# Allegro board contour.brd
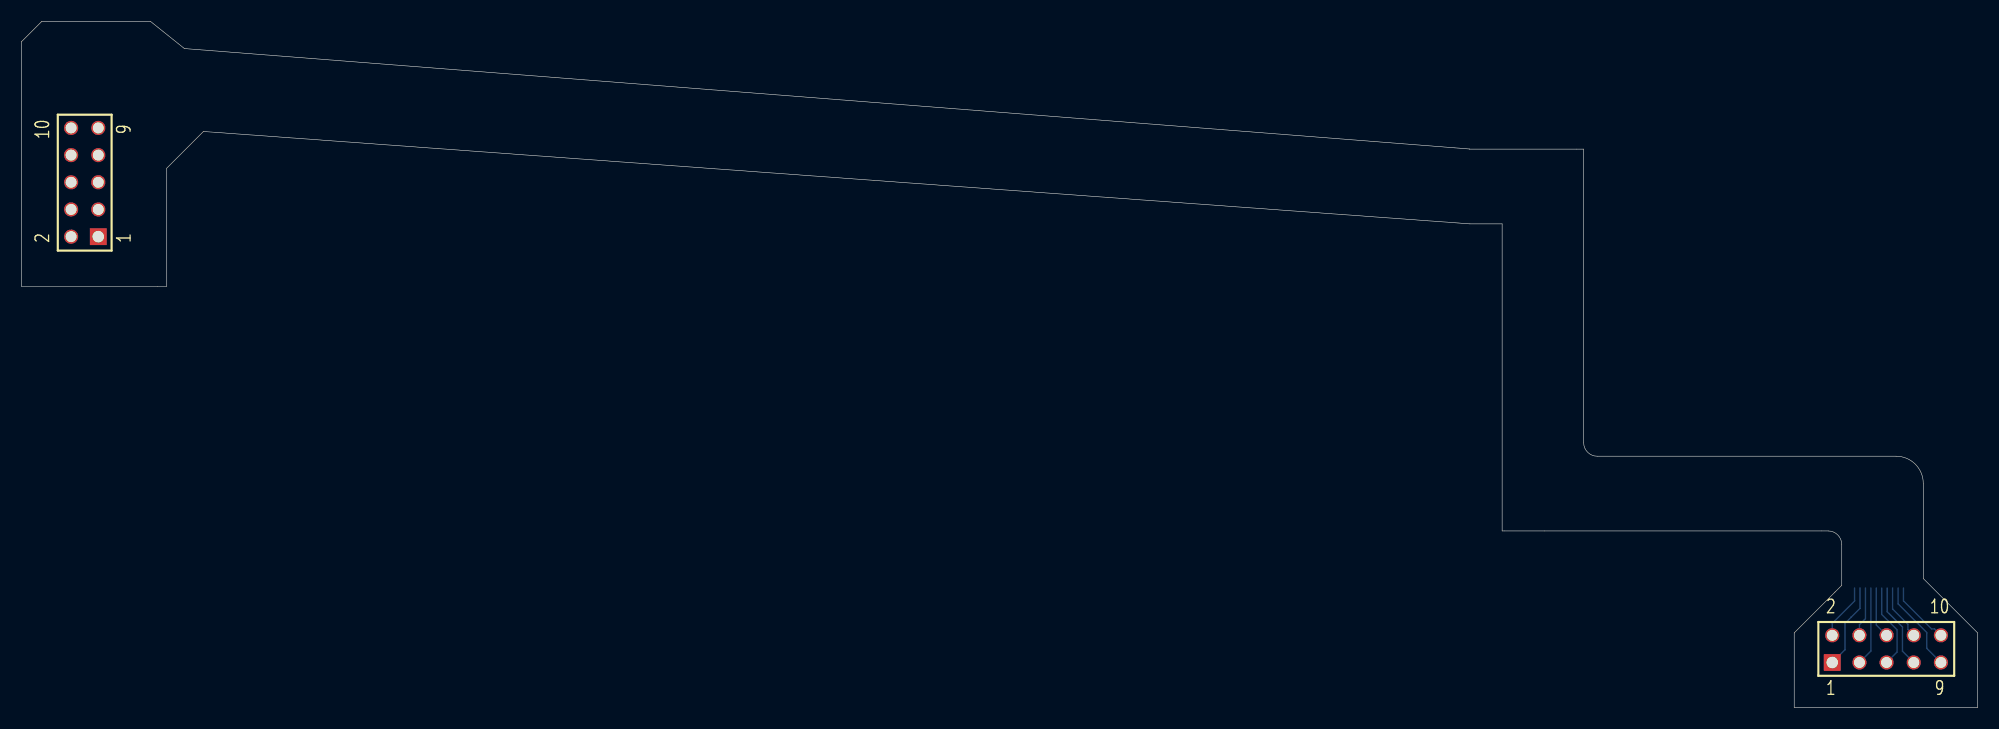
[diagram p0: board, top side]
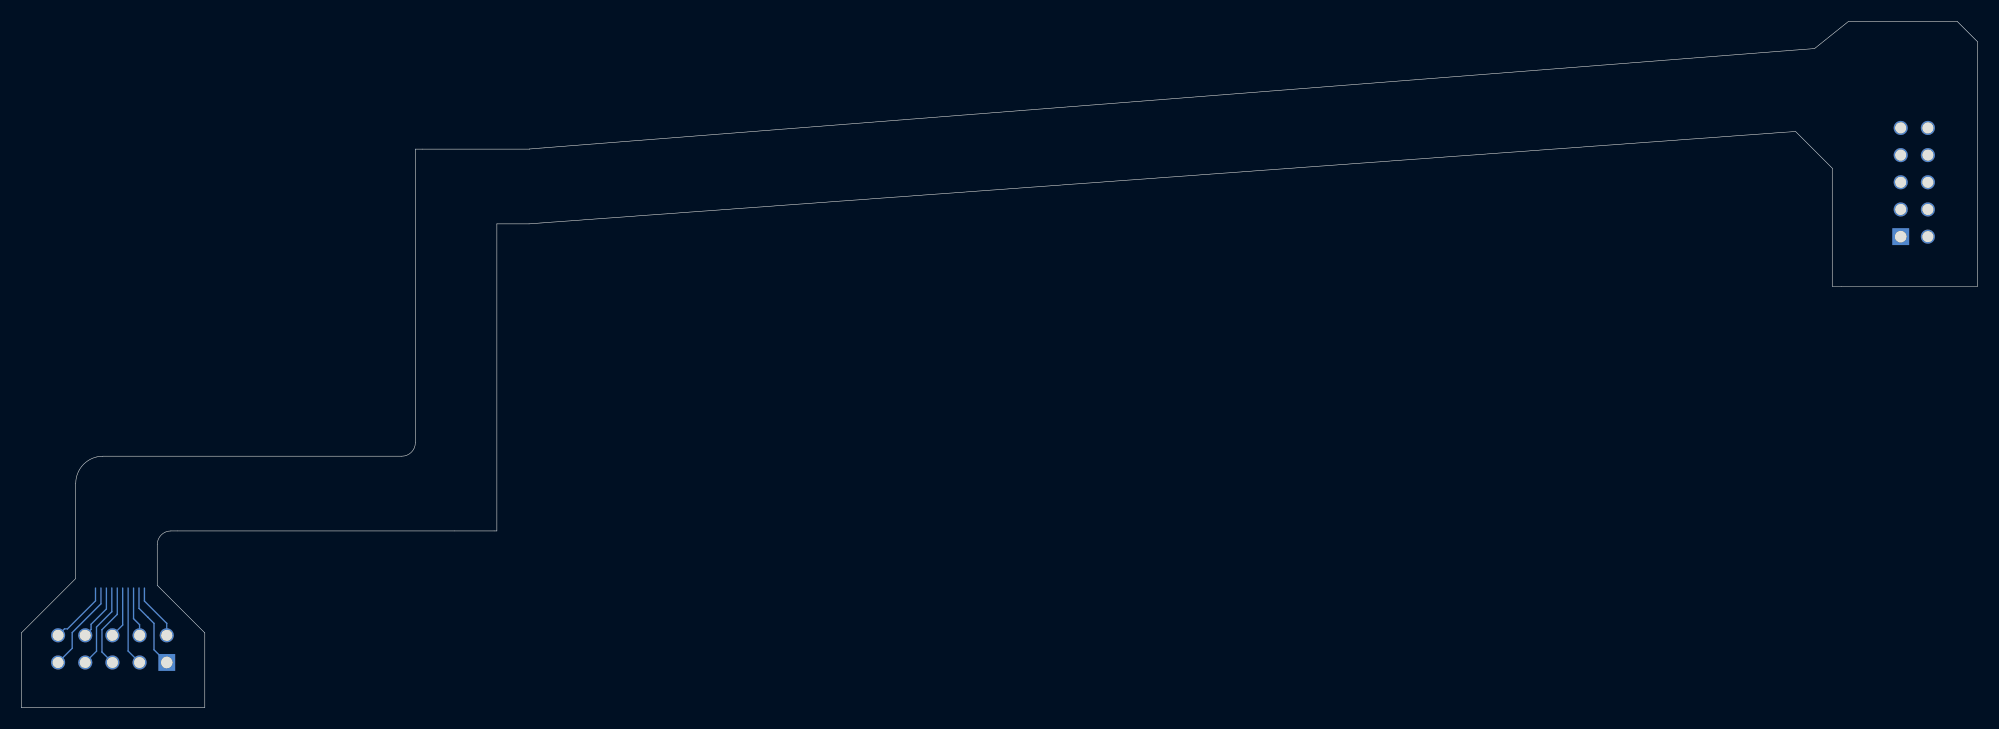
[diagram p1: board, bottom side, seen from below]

Outline 182.88 x 64.13 mm; copper layers: TOP, BOTTOM. Coordinates in mm from the lower left corner of the outline.
Outline path: 0,62.23 1.9,64.13 12.07,64.13 15.24,61.59 135.37,52.21 135.38,52.2 146.05,52.2 146.05,24.76 arc(146.42,23.87) 147.32,23.49 175.26,23.49 arc(177.06,22.75) 177.8,20.95 177.8,12.06 182.88,6.98 182.88,0 165.74,0 165.74,6.98 170.18,11.43 170.18,15.24 arc(169.81,16.14) 168.91,16.51 138.43,16.51 138.43,45.21 135.42,45.21 17.02,53.85 13.59,50.42 13.59,39.37 0,39.37 0,62.23

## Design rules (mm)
constraint set DEFAULT: min track width 0.127

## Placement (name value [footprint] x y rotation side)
J1  -  [HDR_2X5_SAMTEC]  169.29 4.22 0 top
J2  -  [HDR_2X5_SAMTEC]  7.19 44.02 90 top

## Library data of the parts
J1 J2 = 2X5_HEADER: part number: 2X5_HEADER_THRU_HOLE-CONNECTOR,TSW-105-15-F-D

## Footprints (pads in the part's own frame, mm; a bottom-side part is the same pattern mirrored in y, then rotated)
HDR_2X5_SAMTEC
  rect 1.575x1.575 hole 1.067: 1(0,0)
  round 1.321 hole 1.016: 2(0,2.54) 3(2.54,0) 4(2.54,2.54) 5(5.08,0) 6(5.08,2.54) 7(7.62,0) 8(7.62,2.54) 9(10.16,0) 10(10.16,2.54)

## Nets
1: J1.2 J2.1
2: J1.4 J2.3
3: J1.6 J2.5
4: J1.8 J2.8
5: J1.10 J2.10
6: J1.1 J2.2
7: J1.3 J2.4
8: J1.5 J2.6
9: J1.7 J2.7
10: J1.9 J2.9

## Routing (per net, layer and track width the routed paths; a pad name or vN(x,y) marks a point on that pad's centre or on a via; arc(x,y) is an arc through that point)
1: length 5.3
  BOTTOM w0.127: 171.38,11.18 171.38,9.96 169.29,7.87 J1.2
2: length 4.7
  BOTTOM w0.127: 172.39,11.18 172.39,8.31 171.83,7.75 J1.4
3: length 4.8
  BOTTOM w0.127: 173.41,11.18 173.41,7.72 J1.6
4: length 5.2
  BOTTOM w0.127: J1.8 176.36,7.3 176.36,7.79 174.93,9.22 174.93,11.18
5: length 6
  BOTTOM w0.127: 175.95,11.18 175.95,9.98 178.57,7.36 178.85,7.36 J1.10
6: length 8
  BOTTOM w0.127: 171.89,11.18 171.89,9.27 171.05,8.43 171.04,8.43 170.48,7.87 170.48,5.41 J1.1
7: length 7.4
  BOTTOM w0.127: J1.3 172.9,5.29 172.9,11.18
8: length 8
  BOTTOM w0.127: 173.92,11.18 173.92,8.71 175.35,7.28 175.35,5.19 J1.5
9: length 8
  BOTTOM w0.127: J1.7 175.86,5.27 175.86,7.53 174.43,8.96 174.43,11.18
10: length 8.6
  BOTTOM w0.127: J1.9 178.13,5.54 178.13,7.01 175.44,9.7 175.44,11.18
